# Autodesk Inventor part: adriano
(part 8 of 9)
sketch "スケッチ239"
  geometry: L1 (-4.75, 23.036)-(-9.75, 23.036) reference; L2 (-9.75, 23.036)-(-9.75, 20.036) reference; L3 (-9.75, 20.036)-(-4.75, 20.036) reference; L4 (-9.2, 22.536)-(-8.6, 22.536); L5 (-8.6, 22.536)-(-8.6, 20.836); L6 (-8.6, 20.836)-(-9.2, 20.836); L7 (-9.2, 20.836)-(-9.2, 22.536); L8 (-8.1, 22.536)-(-7.5, 22.536); L9 (-7.5, 22.536)-(-7.5, 20.836); L10 (-7.5, 20.836)-(-8.1, 20.836); L11 (-8.1, 20.836)-(-8.1, 22.536); L12 (-7, 22.536)-(-6.4, 22.536); L13 (-6.4, 22.536)-(-6.4, 20.836); L14 (-6.4, 20.836)-(-7, 20.836); L15 (-7, 20.836)-(-7, 22.536); L16 (-5.9, 22.536)-(-5.3, 22.536); L17 (-5.3, 22.536)-(-5.3, 20.836); L18 (-5.3, 20.836)-(-5.9, 20.836); L19 (-5.9, 20.836)-(-5.9, 22.536); L20 (31.3, 22.536)-(31.9, 22.536); L21 (31.9, 22.536)-(31.9, 20.836); L22 (31.9, 20.836)-(31.3, 20.836); L23 (31.3, 20.836)-(31.3, 22.536); L24 (32.4, 22.536)-(33, 22.536); L25 (33, 22.536)-(33, 20.836); L26 (33, 20.836)-(32.4, 20.836); L27 (32.4, 20.836)-(32.4, 22.536); L28 (33.5, 22.536)-(34.1, 22.536); L29 (34.1, 22.536)-(34.1, 20.836); L30 (34.1, 20.836)-(33.5, 20.836); L31 (33.5, 20.836)-(33.5, 22.536); L32 (34.6, 22.536)-(35.2, 22.536); L33 (35.2, 22.536)-(35.2, 20.836); L34 (35.2, 20.836)-(34.6, 20.836); L35 (34.6, 20.836)-(34.6, 22.536); L36 (30.75, 23.036)-(30.75, 20.036) reference; L37 (31.3, 5)-(31.9, 5); L38 (31.9, 5)-(31.9, 3.3); L39 (31.9, 3.3)-(31.3, 3.3); L40 (31.3, 3.3)-(31.3, 5); L41 (32.4, 5)-(33, 5); L42 (33, 5)-(33, 3.3); L43 (33, 3.3)-(32.4, 3.3); L44 (32.4, 3.3)-(32.4, 5); L45 (33.5, 5)-(34.1, 5); L46 (34.1, 5)-(34.1, 3.3); L47 (34.1, 3.3)-(33.5, 3.3); L48 (33.5, 3.3)-(33.5, 5); L49 (34.6, 5)-(35.2, 5); L50 (35.2, 5)-(35.2, 3.3); L51 (35.2, 3.3)-(34.6, 3.3); L52 (34.6, 3.3)-(34.6, 5); L53 (30.75, 2.5)-(35.75, 2.5) reference; L54 (35.75, 5.5)-(30.75, 5.5) reference; L55 (-6.4, 5)-(-7, 5); L56 (-7, 5)-(-7, 3.3); L57 (-7, 3.3)-(-6.4, 3.3); L58 (-6.4, 3.3)-(-6.4, 5); L59 (-7.5, 5)-(-8.1, 5); L60 (-8.1, 5)-(-8.1, 3.3); L61 (-8.1, 3.3)-(-7.5, 3.3); L62 (-7.5, 3.3)-(-7.5, 5); L63 (-8.6, 5)-(-9.2, 5); L64 (-9.2, 5)-(-9.2, 3.3)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; 1 further point
  constraints: 128 end point, 32 parallel, 16 horizontal, 16 perpendicular
  dimensions: "d4034" = 0.5 distance between parallel lines of L11 L5; "d4036" = 0.5 distance between parallel lines of L1 L8; "d4037" = 0 distance between parallel lines of L8 L12; "d4038" = 0 distance between parallel lines of L16 L12; "d4039" = 0 distance between parallel lines of L8 L4; "d4040" = 0.55 distance between parallel lines of L2 L7; "d4041" = 0.5 distance between parallel lines of L15 L9; "d4042" = 0.5 distance between parallel lines of L13 L19; "d4043" = 0.6 distance of L5.end L6.end; "d4044" = 0.6 distance of L9.end L10.end; "d4045" = 0.6 distance of L13.end L14.end; "d4046" = 0.6 distance of L17.end L18.end; "d4047" = 0.8 distance between parallel lines of L3 L6; "d4048" = 0.55 distance between parallel lines of L23 L36; "d4049" = 0.5 distance between parallel lines of L27 L21; "d4050" = 0.5 distance between parallel lines of L31 L25; "d4051" = 0.5 distance between parallel lines of L35 L29; "d4052" = 0.6 distance of L21.end L22.end; "d4053" = 0.6 distance of L25.end L26.end; "d4054" = 0.6 distance of L29.end L30.end; "d4055" = 0.6 distance of L33.end L34.end; "d4056" = 0.8 distance between parallel lines of L53 L39; "d4057" = 0 distance between parallel lines of L43 L39; "d4058" = 0 distance between parallel lines of L43 L47; "d4059" = 0 distance between parallel lines of L51 L47; "d4060" = 0.5 distance between parallel lines of L49 L54; "d4061" = 0 distance between parallel lines of L45 L49; "d4062" = 0 distance between parallel lines of L41 L45; "d4063" = 0 distance between parallel lines of L37 L41
extrude "押し出し228" cut sketch "スケッチ239" distance "d4065" = 0.5; taper "d4066" = 0 deg
fillet "フィレット5" dims "d4067" = 2
chamfer "面取り4" distance "d4068" = 0.4; stored, may be unused: second distance "d4069" = 2, angle "d4070" = 45 deg
sketch "スケッチ240"
  geometry: C1 r 1 at (5.162, -13.34); 1 further point
  constraints: 1 centre point
  dimensions: "d4071" = 2 diameter of C1
extrude "押し出し229" join sketch "スケッチ240" distance "d4073" = 16; taper "d4074" = 0 deg
sketch "スケッチ241"
  geometry: L1 (-0.4, 3)-(0.4, 3); L2 (0.4, 3)-(0.4, -3); L3 (0.4, -3)-(-0.4, -3); L4 (-0.4, -3)-(-0.4, 3); L5 (-3, 0.4)-(3, 0.4); L6 (3, 0.4)-(3, -0.4); L7 (3, -0.4)-(-3, -0.4); L8 (-3, -0.4)-(-3, 0.4); C1 r 1 at (0, 0) reference; 1 further point
  constraints: 16 end point, 4 parallel, 2 horizontal, 2 perpendicular
  dimensions: "d4075" = 6 distance of L1.end L2.end; "d4077" = 6 distance of L5.start L5.end; "d4078" = 0.4 distance from line of L4 C1.centre; "d4079" = 0.8 distance of L2.end L3.end; "d4080" = 0.4 distance from line of L5 C1.centre; "d4081" = 0.8 distance of L7.end L5.start; "d4082" = 3 distance from line of L1 C1.centre; "d4083" = 3 distance from line of L6 C1.centre
extrude "押し出し230" join sketch "スケッチ241" distance "d4084" = 32; taper "d4085" = 0 deg
sketch "スケッチ242"
  geometry: L1 (0.4, -3)-(0.4, -0.4) reference; L2 (0.4, -0.4)-(3, -0.4) reference; L3 (-0.4, 3)-(-0.4, 0.4) reference; L4 (-0.4, 0.4)-(-3, 0.4) reference; L5 (-0.4, 1.7)-(0.4, 1.7); L6 (0.4, 1.7)-(0.4, -1.7); L7 (0.4, -1.7)-(-0.4, -1.7); L8 (-0.4, -1.7)-(-0.4, 1.7); L9 (-1.7, 0.4)-(1.7, 0.4); L10 (1.7, 0.4)-(1.7, -0.4); L11 (1.7, -0.4)-(-1.7, -0.4); L12 (-1.7, -0.4)-(-1.7, 0.4); 1 further point
  constraints: 16 end point, 4 midpoint, 4 parallel, 2 horizontal, 2 perpendicular
extrude "押し出し231" join sketch "スケッチ242" distance "d4086" = 18; taper "d4087" = 0 deg
sketch "スケッチ243"
  geometry: C1 r 0.5 at (0, 0); 1 further point
  constraints: 1 centre point
  dimensions: "d4088" = 1 diameter of C1
extrude "押し出し232" join sketch "スケッチ243" distance "d4091" = 8; taper "d4092" = 0 deg
fillet "フィレット6" dims "d4093" = 1
chamfer "面取り5" distance "d4094" = 2; stored, may be unused: second distance "d4095" = 2, angle "d4096" = 45 deg
sketch "スケッチ244"
  geometry: L1 (112.588, 11.686)-(112.588, -18.314) reference; L2 (103.588, 31.686)-(112.588, 31.686) reference; C1 r 0.5 at (107.588, 23.686); C2 r 0.5 at (107.588, 15.686); C3 r 0.5 at (107.588, 7.686); 1 further point
  constraints: 3 centre point
  dimensions: "d4097" = 8 distance from line of C1.centre L2; "d4098" = 8 distance of C2.centre C1.centre; "d4099" = 8 distance of C3.centre C2.centre; "d4100" = 5 distance from line of C3.centre L1; "d4101" = 0 horizontal distance of C3.centre C2.centre; "d4102" = 0 horizontal distance of C1.centre C2.centre; "d4103" = 1 diameter of C1; "d4104" = 1 diameter of C2; "d4105" = 1 diameter of C3
extrude "table" join sketch "スケッチ244" distance "d4106" = 2; taper "d4107" = 0 deg
sketch "スケッチ245"
  geometry: C1 r 0.5 at (0, 0) reference; C2 r 1.5 at (0, 0); C3 r 1.5 at (0, -8); C4 r 1.5 at (0, -16); 1 further point
  constraints: 3 centre point, 1 coincident
  dimensions: "d4108" = 3 diameter of C2; "d4110" = 3 diameter of C3; "d4111" = 3 diameter of C4; "d4112" = 8 distance of C3.centre C1.centre; "d4113" = 8 distance of C4.centre C3.centre
extrude "押し出し234" join sketch "スケッチ245" distance "d4114" = 0.5; taper "d4115" = 0 deg
sketch "スケッチ246"
  geometry: L1 (113.588, 30.686)-(113.588, 11.686) reference; L2 (103.588, 31.686)-(112.588, 31.686) reference; L3 (106.688, 27.486)-(108.488, 27.486); L4 (108.488, 27.486)-(108.488, 25.686); L5 (108.488, 25.686)-(106.688, 25.686); L6 (106.688, 25.686)-(106.688, 27.486); L7 (109.488, 24.686)-(111.288, 24.686); L8 (111.288, 24.686)-(111.288, 22.886); L9 (111.288, 22.886)-(109.488, 22.886); L10 (109.488, 22.886)-(109.488, 24.686); L11 (105.688, 24.686)-(103.888, 24.686); L12 (103.888, 24.686)-(103.888, 22.886); L13 (103.888, 22.886)-(105.688, 22.886); L14 (105.688, 22.886)-(105.688, 24.686); L15 (106.688, 21.686)-(108.488, 21.686); L16 (108.488, 21.686)-(108.488, 19.886); L17 (108.488, 19.886)-(106.688, 19.886); L18 (106.688, 19.886)-(106.688, 21.686); L19 (106.688, 19.386)-(108.488, 19.386); L20 (108.488, 19.386)-(108.488, 17.586); L21 (108.488, 17.586)-(106.688, 17.586); L22 (106.688, 17.586)-(106.688, 19.386); L23 (109.688, 16.586)-(111.488, 16.586); L24 (111.488, 16.586)-(111.488, 14.786); L25 (111.488, 14.786)-(109.688, 14.786); L26 (109.688, 14.786)-(109.688, 16.586); L27 (105.688, 16.586)-(103.888, 16.586); L28 (103.888, 16.586)-(103.888, 14.786); L29 (103.888, 14.786)-(105.688, 14.786); L30 (105.688, 14.786)-(105.688, 16.586); L31 (106.688, 13.786)-(108.488, 13.786); L32 (108.488, 13.786)-(108.488, 11.986); L33 (108.488, 11.986)-(106.688, 11.986); L34 (106.688, 11.986)-(106.688, 13.786); L35 (106.688, 11.486)-(108.488, 11.486); L36 (108.488, 11.486)-(108.488, 9.686); L37 (108.488, 9.686)-(106.688, 9.686); L38 (106.688, 9.686)-(106.688, 11.486); L39 (109.488, 8.686)-(111.288, 8.686); L40 (111.288, 8.686)-(111.288, 6.886); L41 (111.288, 6.886)-(109.488, 6.886); L42 (109.488, 6.886)-(109.488, 8.686); L43 (106.688, 5.886)-(108.488, 5.886); L44 (108.488, 5.886)-(108.488, 4.086); L45 (108.488, 4.086)-(106.688, 4.086); L46 (106.688, 4.086)-(106.688, 5.886); L47 (104.427, 8.486)-(104.688, 6.705); L48 (104.688, 6.705)-(102.907, 6.444); L49 (102.907, 6.444)-(102.646, 8.225); L50 (102.646, 8.225)-(104.427, 8.486); 1 further point
  constraints: 96 end point, 24 parallel, 12 perpendicular, 11 horizontal
  dimensions: "d4124" = 1.8 distance of L3.end L4.end; "d4126" = 1.8 distance of L7.end L8.end; "d4127" = 1.8 distance of L3.start L3.end; "d4128" = 2.3 distance between parallel lines of L8 L1; "d4129" = 1 distance between parallel lines of L10 L4; "d4130" = 1.8 distance of L7.start L7.end; "d4131" = 4.2 distance between parallel lines of L3 L2; "d4132" = 1 distance between parallel lines of L7 L5; "d4133" = 1.8 distance of L11.start L11.end; "d4134" = 1 distance between parallel lines of L6 L14; "d4135" = 1.8 distance of L15.end L16.end; "d4136" = 1.2 distance between parallel lines of L15 L9; "d4137" = 1.8 distance of L21.end L19.start; "d4138" = 0 distance between parallel lines of L7 L11; "d4139" = 0 distance between parallel lines of L9 L13; "d4140" = 0 distance between parallel lines of L16 L4; "d4141" = 0 distance between parallel lines of L18 L6; "d4142" = 0 distance between parallel lines of L22 L18; "d4143" = 0 distance between parallel lines of L20 L16; "d4144" = 0.5 distance between parallel lines of L19 L17; "d4145" = 1 distance between parallel lines of L23 L21; "d4146" = 1.8 distance of L23.end L24.end; "d4147" = 1 distance between parallel lines of L31 L25; "d4148" = 1.8 distance of L31.end L32.end; "d4149" = 0.5 distance between parallel lines of L35 L33; "d4150" = 1.8 distance of L35.end L36.end; "d4151" = 1 distance between parallel lines of L39 L37; "d4152" = 1.8 distance of L39.end L40.end; "d4153" = 1.8 distance of L43.end L44.end; "d4154" = 1 distance between parallel lines of L43 L41; "d4155" = 2 distance from line of L46 L47.end; "d4156" = 0 distance between parallel lines of L46 L38; "d4157" = 0 distance between parallel lines of L38 L34; "d4158" = 1.8 distance of L31.start L31.end; "d4159" = 0 distance between parallel lines of L32 L20; "d4161" = 1.8 distance between parallel lines of L47 L49; "d4162" = 1.8 distance between parallel lines of L48 L50; "d4163" = 1.2 distance from line of L47.start L37; "d4365" = 0 distance between parallel lines of L28 L12; "d4366" = 2.1 distance between parallel lines of L1 L24; "d4367" = 1.8 distance between parallel lines of L24 L26
extrude "押し出し235" join sketch "スケッチ246" distance "d4164" = 3; taper "d4165" = 0 deg
sketch "スケッチ247"
  geometry: L1 (106.688, 27.486)-(106.688, 25.686) reference; L2 (108.488, 25.686)-(108.488, 27.486) reference; L3 (109.488, 24.687)-(110.688, 24.687); L4 (110.688, 24.687)-(110.688, 22.886); L5 (110.688, 22.886)-(109.488, 22.886); L6 (109.488, 22.886)-(109.488, 24.687); L7 (105.688, 24.687)-(104.488, 24.687); L8 (104.488, 24.687)-(104.488, 22.886); L9 (104.488, 22.886)-(105.688, 22.886); L10 (105.688, 22.886)-(105.688, 24.687); L11 (106.688, 21.686)-(108.488, 21.686); L12 (108.488, 21.686)-(108.488, 20.486); L13 (108.488, 20.486)-(106.688, 20.486); L14 (106.688, 20.486)-(106.688, 21.686); L15 (106.688, 17.586)-(108.488, 17.586); L16 (108.488, 17.586)-(108.488, 18.786); L17 (108.488, 18.786)-(106.688, 18.786); L18 (106.688, 18.786)-(106.688, 17.586); L19 (105.688, 16.586)-(104.488, 16.586); L20 (104.488, 16.586)-(104.488, 14.786); L21 (104.488, 14.786)-(105.688, 14.786); L22 (105.688, 14.786)-(105.688, 16.586); L23 (109.688, 16.586)-(110.888, 16.586); L24 (110.888, 16.586)-(110.888, 14.786); L25 (110.888, 14.786)-(109.688, 14.786); L26 (109.688, 14.786)-(109.688, 16.586); L27 (106.688, 13.786)-(108.488, 13.786); L28 (108.488, 13.786)-(108.488, 12.586); L29 (108.488, 12.586)-(106.688, 12.586); L30 (106.688, 12.586)-(106.688, 13.786); L31 (106.688, 9.686)-(108.488, 9.686); L32 (108.488, 9.686)-(108.488, 10.886); L33 (108.488, 10.886)-(106.688, 10.886); L34 (106.688, 10.886)-(106.688, 9.686); L35 (109.488, 8.686)-(110.688, 8.686); L36 (110.688, 8.686)-(110.688, 6.872); L37 (110.688, 6.872)-(109.488, 6.872); L38 (109.488, 6.872)-(109.488, 8.686); L39 (106.688, 5.886)-(108.488, 5.886); L40 (108.488, 5.886)-(108.488, 4.686); L41 (108.488, 4.686)-(106.688, 4.686); L42 (106.688, 4.686)-(106.688, 5.886); L43 (106.688, 26.886)-(108.488, 26.886); L44 (108.488, 26.886)-(108.488, 25.686); L45 (108.488, 25.686)-(106.688, 25.686); L46 (106.688, 25.686)-(106.688, 26.886); L47 (103.888, 24.686)-(103.888, 22.886) reference; L48 (103.888, 22.886)-(105.688, 22.886) reference; L49 (109.488, 22.886)-(111.288, 22.886) reference; L50 (108.488, 21.686)-(106.688, 21.686) reference; L51 (106.688, 17.586)-(108.488, 17.586) reference; L52 (109.688, 16.586)-(109.688, 14.786) reference; L53 (111.488, 16.586)-(109.688, 16.586) reference; L54 (105.688, 14.786)-(105.688, 16.586) reference; L55 (103.888, 14.786)-(105.688, 14.786) reference; L56 (106.688, 9.686)-(108.488, 9.686) reference; L57 (108.488, 13.786)-(106.688, 13.786) reference; L58 (109.488, 8.686)-(109.488, 6.886) reference; L59 (111.288, 8.686)-(109.488, 8.686) reference; L60 (108.488, 5.886)-(106.688, 5.886) reference; L61 (104.515, 8.586)-(104.788, 6.706); L62 (104.788, 6.706)-(103.502, 6.519); L63 (103.502, 6.519)-(103.228, 8.399); L64 (103.228, 8.399)-(104.515, 8.586)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; 1 further point
  constraints: 96 end point, 24 parallel, 12 perpendicular, 11 horizontal, 6 point on line
  dimensions: "d4166" = 1.2 distance of L43.end L2.start; "d4167" = 1.2 distance of L3.start L3.end; "d4168" = 1.2 distance of L7.start L7.end; "d4169" = 0.6 distance between parallel lines of L47 L8; "d4170" = 0 distance between parallel lines of L9 L48; "d4171" = 0 distance between parallel lines of L5 L49; "d4172" = 1.2 distance of L11.end L12.end; "d4173" = 0 distance between parallel lines of L50 L11; "d4174" = 1.2 distance of L15.end L16.end; "d4175" = 0 distance between parallel lines of L51 L15; "d4176" = 1.2 distance of L23.start L23.end; "d4177" = 0 distance between parallel lines of L52 L26; "d4178" = 0 distance between parallel lines of L23 L53; "d4179" = 0 distance between parallel lines of L22 L54; "d4180" = 1.2 distance of L19.start L19.end; "d4181" = 0 distance between parallel lines of L55 L21; "d4182" = 1.8 distance of L19.end L20.end; "d4183" = 1.8 distance of L23.end L24.end; "d4184" = 1.2 distance of L27.end L28.end; "d4185" = 1.2 distance of L31.end L32.end; "d4186" = 0 distance between parallel lines of L31 L56; "d4187" = 0 distance between parallel lines of L27 L57; "d4188" = 1.2 distance of L35.start L35.end; "d4189" = 0 distance between parallel lines of L38 L58; "d4190" = 0 distance between parallel lines of L59 L35; "d4191" = 0 distance between parallel lines of L60 L39; "d4192" = 1.2 distance of L39.end L40.end; "d4193" = 1.3 distance between parallel lines of L61 L63; "d4194" = 1.9 distance between parallel lines of L62 L64; "d4197" = 1.8 distance of L32.end L33.end; "d4198" = 1.9 distance from line of L42 L61.end; "d4199" = 0 distance between parallel lines of L42 L34; "d4200" = 1.1 distance from line of L31 L61.start; "d4203" = 0 distance between parallel lines of L6 L66; "d4368" = 0 distance between parallel lines of L18 L14
extrude "押し出し236" cut sketch "スケッチ247" distance "d4201" = 1.5; taper "d4202" = 0 deg
sketch "スケッチ249"
  geometry: L1 (1.8, 0)-(0, 0) reference; L2 (0.6, 0)-(1.2, 0); L3 (1.2, 0)-(1.2, 0.6); L4 (1.2, 0.6)-(0.6, 0.6); L5 (0.6, 0.6)-(0.6, 0); 1 further point
  constraints: 8 end point, 2 parallel, 1 horizontal, 1 perpendicular, 1 point on line
  dimensions: "d4204" = 0.6 distance of L2.end L3.end; "d4206" = 0.6 distance of L3.end L4.end
extrude "押し出し237" cut sketch "スケッチ249" distance "d4207" = 20; taper "d4208" = 0 deg
sketch "スケッチ250"
  geometry: L1 (1.8, 0)-(0, 0) reference; L2 (1.2, 0)-(0.6, 0); L3 (0.6, 0)-(0.6, 0.6); L4 (0.6, 0.6)-(1.2, 0.6); L5 (1.2, 0.6)-(1.2, 0); 1 further point
  constraints: 8 end point, 2 parallel, 1 horizontal, 1 perpendicular, 1 point on line
  dimensions: "d4209" = 0.6 distance of L4.end L2.start; "d4211" = 0.6 distance of L3.end L4.end
extrude "押し出し238" cut sketch "スケッチ250" distance "d4212" = 12; taper "d4213" = 0 deg
sketch "スケッチ251"
  geometry: L1 (-0.952, -0.5)-(-1.8, -0.5) reference; L2 (-1.376, -0.5)-(-0.826, -0.5); L3 (-0.826, -0.5)-(-0.826, 0.1); L4 (-0.826, 0.1)-(-1.376, 0.1); L5 (-1.376, 0.1)-(-1.376, -0.5); 2 further points
  constraints: 8 end point, 2 parallel, 1 horizontal, 1 midpoint, 1 perpendicular
  dimensions: "d4214" = 0.6 distance of L4.end L2.start; "d4216" = 0.55 distance of L3.end L4.end
extrude "押し出し239" cut sketch "スケッチ251" distance "d4217" = 4; taper "d4218" = 0 deg
sketch "スケッチ253"
  geometry: L1 (1.8, 0)-(0, 0) reference; L2 (0.6, 0)-(1.2, 0); L3 (1.2, 0)-(1.2, 0.6); L4 (1.2, 0.6)-(0.6, 0.6); L5 (0.6, 0.6)-(0.6, 0); L6 (6.4, 0.6)-(7, 0.6); L7 (7, 0.6)-(7, 0); L8 (7, 0)-(6.4, 0); L9 (6.4, 0)-(6.4, 0.6); L10 (8.8, 0.6)-(9.4, 0.6); L11 (9.4, 0.6)-(9.4, 0); L12 (9.4, 0)-(8.8, 0); L13 (8.8, 0)-(8.8, 0.6); L14 (14.4, 0.6)-(15, 0.6); L15 (15, 0.6)-(15, 0); L16 (15, 0)-(14.4, 0); L17 (14.4, 0)-(14.4, 0.6); L18 (16.6, 0.6)-(17.2, 0.6); L19 (17.2, 0.6)-(17.2, 0); L20 (17.2, 0)-(16.6, 0); L21 (16.6, 0)-(16.6, 0.6); L22 (22.2, 0.6)-(22.8, 0.6); L23 (22.8, 0.6)-(22.8, 0); L24 (22.8, 0)-(22.2, 0); L25 (22.2, 0)-(22.2, 0.6); 1 further point
  constraints: 48 end point, 12 parallel, 6 horizontal, 6 perpendicular, 5 point on line
  dimensions: "d4219" = 0.6 distance of L3.end L4.end; "d4221" = 0.6 distance of L6.start L6.end; "d4222" = 0.6 distance of L10.start L10.end; "d4223" = 0.6 distance of L14.start L14.end; "d4224" = 0.6 distance of L18.start L18.end; "d4225" = 5.2 distance between parallel lines of L9 L3; "d4226" = 1.8 distance between parallel lines of L13 L7; "d4227" = 5 distance between parallel lines of L17 L11; "d4228" = 1.6 distance between parallel lines of L21 L15; "d4229" = 0.6 distance of L22.start L22.end; "d4230" = 5 distance between parallel lines of L25 L19; "d4231" = 0.6 distance of L2.end L3.end; "d4232" = 0 distance between parallel lines of L6 L4; "d4233" = 0 distance between parallel lines of L24 L20
extrude "押し出し240" cut sketch "スケッチ253" distance "d4234" = 3; taper "d4235" = 0 deg
fillet "フィレット7" dims "d4236" = 0.5
fillet "フィレット11" dims "d4240" = 2
sketch "スケッチ254"
  geometry: L1 (-0.115, 24.135)-(0.885, 24.135); L2 (0.885, 24.135)-(0.885, -0.31); L3 (0.885, -0.31)-(-0.115, -0.31); L4 (-0.115, -0.31)-(-0.115, 24.135); L5 (0.785, -0.634)-(0.785, 24.113) reference; 1 further point
  constraints: 8 end point, 2 parallel, 1 horizontal, 1 perpendicular
  dimensions: "d4243" = 1 distance of L2.end L3.end; "d4245" = 0.1 distance between parallel lines of L5 L2
extrude "押し出し241" join sketch "スケッチ254" distance "d4241" = 0.5; taper "d4242" = 0 deg
sketch "スケッチ255"
  geometry: L1 (0.001, 0.961)-(24.532, 0.961); L2 (24.532, 0.961)-(24.532, -0.039); L3 (24.532, -0.039)-(0.001, -0.039); L4 (0.001, -0.039)-(0.001, 0.961); 1 further point
  constraints: 8 end point, 2 parallel, 1 horizontal, 1 perpendicular
  dimensions: "d4246" = 1 distance of L1.end L2.end
extrude "押し出し242" join sketch "スケッチ255" distance "d4248" = 0.5; taper "d4249" = 0 deg; dims "d1246" = 0
sketch "スケッチ256"
  geometry: L1 (24.669, -0.79)-(24.671, -0.696) reference; L2 (24.671, -0.696)-(24.029, 0) reference; L3 (24.029, 0)-(0, 0) reference; L4 (0, 0)-(-0.428, -0.262) reference; L5 (-0.439, -0.79)-(-0.428, -0.262) reference; L6 (-0.439, -0.79)-(24.669, -0.79) reference; L7 (-0.455, 0.138)-(24.487, 0.138); L8 (24.487, 0.138)-(24.487, -0.862); L9 (24.487, -0.862)-(-0.455, -0.862); L10 (-0.455, -0.862)-(-0.455, 0.138); 1 further point
  constraints: 8 end point, 2 parallel, 1 horizontal, 1 perpendicular
  dimensions: "d4250" = 1 distance of L7.end L8.end
extrude "押し出し243" join sketch "スケッチ256" distance "d4252" = 0.5; taper "d4253" = 0 deg
sketch "スケッチ258"
  geometry: L1 (-24.462, -0.711)-(-24.462, -0.787) reference; L2 (-24.531, -0.79)-(0, 0) reference; L3 (0, 0)-(0, 0.525) reference; L4 (0, 0.525)-(-0.412, 0.769) reference; L5 (-0.412, 0.769)-(-23.824, 0.015) reference; L6 (-23.824, 0.015)-(-24.531, -0.79) reference; L7 (-0.015, 0.9)-(-24.313, 0.118); L8 (-24.313, 0.118)-(-24.281, -0.882); L9 (-24.281, -0.882)-(0.017, -0.1); L10 (0.017, -0.1)-(-0.015, 0.9); 1 further point
  constraints: 8 end point, 2 parallel, 2 perpendicular
  dimensions: "d4254" = 1 distance between parallel lines of L9 L7; "d4257" = 0.1 distance between parallel lines of L9 L2
extrude "押し出し244" join sketch "スケッチ258" distance "d4258" = 0.5; taper "d4259" = 0 deg
sketch "スケッチ259"
  geometry: L1 (0, 23.758)-(0, 0) reference; L2 (0.781, 0.02)-(0.781, 24.416) reference; L3 (-0.119, 24.077)-(-0.119, -0.044); L4 (-0.119, -0.044)-(0.881, -0.044); L5 (0.881, -0.044)-(0.881, 24.077); L6 (0.881, 24.077)-(-0.119, 24.077); 1 further point
  constraints: 8 end point, 2 parallel, 2 perpendicular
  dimensions: "d4260" = 1 distance of L5.end L3.start; "d4262" = 0.1 distance between parallel lines of L2 L5
extrude "押し出し245" join sketch "スケッチ259" distance "d4263" = 0.5; taper "d4264" = 0 deg; dims "d1290" = 0, "d1292" = 0
sketch "スケッチ260"
  geometry: L1 (0.737, 25.022)-(0.643, 25.022) reference; L2 (0.643, 25.022)-(0, 0) reference; L3 (0, 0)-(0.789, 0) reference; L4 (0.789, 0)-(1.416, 24.368) reference; L5 (1.416, 24.368)-(0.737, 25.022) reference; L6 (0.524, 24.718)-(-0.113, -0.039); L7 (-0.113, -0.039)-(0.887, -0.065); L8 (0.887, -0.065)-(1.524, 24.693); L9 (1.524, 24.693)-(0.524, 24.718); 1 further point
  constraints: 8 end point, 2 parallel, 2 perpendicular
  dimensions: "d4265" = 1 horizontal distance of L8.end L6.start; "d4267" = 0.1 distance between parallel lines of L4 L8
extrude "押し出し246" join sketch "スケッチ260" distance "d4268" = 0.5; taper "d4269" = 0 deg; dims "d1285" = 0
sketch "スケッチ261"
  geometry: L1 (-0.25, 1.6)-(0.25, 1.6); L2 (0.25, 1.6)-(0.25, -0.2); L3 (0.25, -0.2)-(-0.25, -0.2); L4 (-0.25, -0.2)-(-0.25, 1.6); L5 (-0.3, -0.15)-(-0.072, 0.295); L6 (-0.072, 0.295)-(1.174, -0.344); L7 (1.174, -0.344)-(0.946, -0.789); L8 (0.946, -0.789)-(-0.3, -0.15); C1 r 2.024 at (0, 0) reference; 1 further point
  constraints: 16 end point, 4 parallel, 2 perpendicular, 1 horizontal
  dimensions: "d4270" = 0.5 distance of L1.start L1.end; "d4272" = 0.25 distance from line of L2 C1.centre; "d4273" = 0.2 distance from line of L3 C1.centre; "d4274" = 1.8 distance of L3.end L1.start; "d4275" = 0.5 distance between parallel lines of L8 L6; "d4276" = 1.4 distance between parallel lines of L7 L5; "d4277" = 0.3 horizontal distance of C1.centre L5.start; "d4278" = 1.75 distance from line of L5.start L1
extrude "押し出し247" join sketch "スケッチ261" distance "d4279" = 0.5; taper "d4280" = 0 deg
sketch "スケッチ262"
  geometry: C1 r 0.2 at (0, 0); 1 further point
  constraints: 1 centre point
  dimensions: "d4281" = 0.4 diameter of C1
extrude "押し出し248" join sketch "スケッチ262" distance "d4285" = 0.5; taper "d4286" = 0 deg
sketch "スケッチ263"
  geometry: C1 r 0.3 at (0, 0) reference; C2 r 0.5 at (0, 0) reference; C3 r 0.8 at (0, 0); 1 further point
  constraints: 1 centre point, 1 coincident
  dimensions: "d4287" = 1.6 diameter of C3
extrude "押し出し249" join sketch "スケッチ263" distance "d4289" = 0.4; taper "d4290" = 0 deg
fillet "フィレット12" dims "d4291" = 0.2
fillet "フィレット13" dims "d4292" = 0.2
sketch "スケッチ264"
  geometry: L1 (-20.412, 19.314)-(-14.412, 19.314); L2 (-14.412, 19.314)-(-14.412, 13.314); L3 (-14.412, 13.314)-(-20.412, 13.314); L4 (-20.412, 13.314)-(-20.412, 19.314); 1 further point
  constraints: 8 end point, 2 parallel, 1 horizontal, 1 perpendicular
  dimensions: "d4293" = 6 distance of L1.start L1.end; "d4294" = 6 distance of L3.end L1.start
extrude "押し出し250" join sketch "スケッチ264" distance "d4295" = 38; taper "d4296" = 0 deg
fillet "フィレット15" dims "d4313" = 1
sketch "スケッチ268"
  geometry: L1 (119.588, -39.314)-(119.588, 40.686) reference; L2 (117.388, -36.358)-(118.588, -36.358); L3 (118.588, -36.358)-(118.588, -37.558); L4 (118.588, -37.558)-(117.388, -37.558); L5 (117.388, -37.558)-(117.388, -36.358); L6 (117.388, -31.158)-(118.588, -31.158); L7 (118.588, -31.158)-(118.588, -32.358); L8 (118.588, -32.358)-(117.388, -32.358); L9 (117.388, -32.358)-(117.388, -31.158); L10 (117.388, -25.958)-(118.588, -25.958); L11 (118.588, -25.958)-(118.588, -27.158); L12 (118.588, -27.158)-(117.388, -27.158); L13 (117.388, -27.158)-(117.388, -25.958); L14 (117.388, -20.758)-(118.588, -20.758); L15 (118.588, -20.758)-(118.588, -21.958); L16 (118.588, -21.958)-(117.388, -21.958); L17 (117.388, -21.958)-(117.388, -20.758); 1 further point
  constraints: 32 end point, 8 parallel, 4 horizontal, 4 perpendicular
  dimensions: "d4327" = 1.2 distance of L2.end L3.end; "d4328" = 4 distance between parallel lines of L8 L2; "d4329" = 4 distance between parallel lines of L12 L6; "d4330" = 4 distance between parallel lines of L10 L16; "d4331" = 1.2 distance of L6.end L7.end; "d4332" = 1.2 distance of L10.end L11.end; "d4333" = 1.2 distance of L14.end L15.end; "d4334" = 1.2 distance of L3.end L4.end; "d4335" = 1 distance between parallel lines of L1 L3; "d4336" = 0 distance between parallel lines of L9 L5; "d4337" = 0 distance between parallel lines of L13 L9; "d4338" = 0 distance between parallel lines of L17 L13
extrude "押し出し253" join sketch "スケッチ268" distance "d4339" = 1; taper "d4340" = 0 deg
sketch "スケッチ269"
  geometry: L1 (118.588, -36.358)-(117.388, -36.358) reference; L2 (118.588, -37.558)-(118.588, -36.358) reference; L3 (118.588, -37.558)-(116.588, -37.558); L4 (116.588, -37.558)-(116.588, -36.358); L5 (116.588, -36.358)-(118.588, -36.358); L6 (118.588, -36.358)-(118.588, -37.558); L7 (118.588, -32.358)-(116.588, -32.358); L8 (116.588, -32.358)-(116.588, -31.158); L9 (116.588, -31.158)-(118.588, -31.158); L10 (118.588, -31.158)-(118.588, -32.358); L11 (118.588, -27.158)-(116.588, -27.158); L12 (116.588, -27.158)-(116.588, -25.958); L13 (116.588, -25.958)-(118.588, -25.958); L14 (118.588, -25.958)-(118.588, -27.158); L15 (118.588, -21.958)-(116.588, -21.958); L16 (116.588, -21.958)-(116.588, -20.758); L17 (116.588, -20.758)-(118.588, -20.758); L18 (118.588, -20.758)-(118.588, -21.958); 1 further point
  constraints: 32 end point, 8 parallel, 4 horizontal, 4 perpendicular
  dimensions: "d4341" = 2 distance of L2.start L3.end; "d4342" = 0 distance between parallel lines of L4 L8; "d4343" = 0 distance between parallel lines of L12 L8; "d4344" = 0 distance between parallel lines of L12 L16; "d4345" = 0 distance between parallel lines of L10 L2; "d4346" = 0 distance between parallel lines of L10 L14; "d4347" = 0 distance between parallel lines of L14 L18; "d4348" = 4 distance between parallel lines of L1 L7; "d4349" = 1.2 distance of L9.end L7.start; "d4350" = 4 distance between parallel lines of L11 L9; "d4351" = 1.2 distance of L13.end L11.start; "d4352" = 4 distance between parallel lines of L15 L13; "d4353" = 1.2 distance of L17.end L15.start
extrude "押し出し254" join sketch "スケッチ269" distance "d4354" = 1; taper "d4355" = 0 deg
fillet "フィレット16" dims "d4356" = 0.5
sketch "スケッチ270"
  geometry: L1 (0.8, 2.6)-(1.8, 2.6) reference; L2 (0.8, 2.6)-(1.8, 2.6); A1 r 0.5 centre (1.3, 2.6) between (1.8, 2.6) and (0.8, 2.6); 1 further point
  constraints: 2 end point, 2 point on circle, 1 centre point, 1 collinear, 1 midpoint
extrude "押し出し255" cut sketch "スケッチ270" distance "d4357" = 5; taper "d4358" = 0 deg
sketch "スケッチ271"
  geometry: L1 (0.8, 2.6)-(1.8, 2.6) reference; L2 (0.8, 2.6)-(1.8, 2.6); A1 r 0.5 centre (1.3, 2.6) between (1.8, 2.6) and (0.8, 2.6); 1 further point
  constraints: 2 end point, 2 point on circle, 1 centre point, 1 collinear, 1 midpoint
extrude "押し出し256" cut sketch "スケッチ271" distance "d4359" = 5; taper "d4360" = 0 deg
sketch "スケッチ272"
  geometry: L1 (60.088, -11.414)-(29.643, -11.414) reference; L2 (29.088, -10.858)-(29.643, -11.414) reference; L3 (29.088, -10.858)-(29.088, 10.23) reference; L4 (29.088, 10.23)-(29.007, 10.149) reference; L5 (29.007, 10.149)-(28.978, 10.179) reference; L6 (28.978, 10.179)-(29.688, 10.883) reference; L7 (29.688, 10.883)-(29.714, 10.857) reference; L8 (29.714, 10.857)-(29.643, 10.786) reference; L9 (29.643, 10.786)-(60.088, 10.786) reference; L10 (58.588, -11.414)-(29.088, -11.414); L11 (29.088, -11.414)-(29.088, -9.414); L12 (29.088, -9.414)-(58.588, -9.414); L13 (58.588, -9.414)-(58.588, -11.414); L14 (58.588, 10.786)-(29.088, 10.786); L15 (29.088, 10.786)-(29.088, 8.786); L16 (29.088, 8.786)-(58.588, 8.786); L17 (58.588, 8.786)-(58.588, 10.786); 1 further point
  constraints: 16 end point, 4 parallel, 4 point on line, 2 horizontal, 2 perpendicular
  dimensions: "d4369" = 2 distance of L14.end L15.end; "d4371" = 2 distance of L10.end L11.end
extrude "押し出し257" join sketch "スケッチ272" distance "d4372" = 2; taper "d4373" = 0 deg
fillet "フィレット17" dims "d4374" = 1
sketch "スケッチ283"
  geometry: L1 (-20.412, 19.314)-(11.588, 19.314) reference; L2 (-19.412, 19.314)-(-73.412, 19.314); L3 (-73.412, 19.314)-(-73.412, 16.314); L4 (-73.412, 16.314)-(-79.412, 16.314); L5 (-79.412, 16.314)-(-79.412, -10.686); L6 (-79.412, -10.686)-(-54.412, -10.686); L7 (-54.412, -10.686)-(-39.412, -20.686); L8 (-39.412, -20.686)-(-19.412, -20.686); L9 (-19.412, -20.686)-(-19.412, 19.314); L10 (-20.412, -15.686)-(-20.412, 19.314) reference; L11 (-20.412, -10.686)-(2.388, -10.686) reference; 1 further point
  constraints: 16 end point, 5 perpendicular, 1 horizontal, 1 parallel, 1 point on line
  dimensions: "d4426" = 1 distance between parallel lines of L10 L9; "d4427" = 3 distance of L2.end L3.end; "d4428" = 6 distance of L3.end L4.end; "d4429" = 0 distance between parallel lines of L6 L11; "d4430" = 40 distance of L8.end L2.start; "d4431" = 20 distance of L7.end L8.end; "d4432" = 25 distance of L5.end L6.end; "d4433" = 60 distance between parallel lines of L5 L9
extrude "押し出し266" join sketch "スケッチ283" distance "d4434" = 40; taper "d4435" = 0 deg
sketch "スケッチ284"
  geometry: L1 (-20.412, 19.686)-(-39.412, 19.686); L2 (-19.412, 20.686)-(-39.412, 20.686) reference; L3 (-39.412, 19.686)-(-54.412, 9.686); L4 (-54.412, 9.686)-(-72.412, 9.686); L5 (-72.412, 9.686)-(-72.412, -18.314); L6 (-72.412, -18.314)-(-20.412, -18.314); L7 (-20.412, -19.314)-(-20.412, 10.686) reference; L8 (-20.412, 19.686)-(-20.412, -18.314); L9 (-19.412, 10.686)-(-19.412, 20.686) reference; L10 (-73.412, -19.314)-(-20.412, -19.314) reference; L11 (-73.412, -16.314)-(-73.412, -19.314) reference; L12 (-54.412, 10.686)-(-79.412, 10.686) reference; 1 further point
  constraints: 12 end point, 2 parallel, 2 perpendicular, 1 point on line
  dimensions: "d4436" = 1 distance from line of L9 L1.start; "d4437" = 1 distance between parallel lines of L2 L1; "d4438" = 1 distance between parallel lines of L6 L10; "d4439" = 1 distance between parallel lines of L11 L5; "d4440" = 1 distance between parallel lines of L12 L4; "d4441" = 0 horizontal distance of L12.start L3.end
extrude "押し出し267" cut sketch "スケッチ284" distance "d4442" = 4; taper "d4443" = 0 deg
sketch "スケッチ285"
  geometry: L1 (-20.412, 19.686)-(-20.412, 10.686) reference; L2 (-20.412, -18.314)-(-72.412, -18.314) reference; L3 (-20.412, 19.686)-(-35.412, 19.686); L4 (-35.412, 19.686)-(-35.412, -18.314); L5 (-35.412, -18.314)-(-20.412, -18.314); L6 (-20.412, -18.314)-(-20.412, 19.686); 1 further point
  constraints: 8 end point, 2 parallel, 1 horizontal, 1 perpendicular, 1 point on line
  dimensions: "d4444" = 15 distance between parallel lines of L4 L6
extrude "押し出し268" cut sketch "スケッチ285" distance "d4445" = 0.5; taper "d4446" = 0 deg
sketch "スケッチ286"
  geometry: L1 (-20.412, 19.686)-(-20.412, 10.686) reference; L2 (-20.412, -18.314)-(-35.412, -18.314) reference; L3 (-20.412, 19.686)-(-30.412, 19.686); L4 (-30.412, 19.686)-(-30.412, -18.314); L5 (-30.412, -18.314)-(-20.412, -18.314); L6 (-20.412, -18.314)-(-20.412, 19.686); 1 further point
  constraints: 8 end point, 2 parallel, 1 horizontal, 1 perpendicular, 1 point on line
  dimensions: "d4447" = 10 distance between parallel lines of L4 L6
extrude "押し出し269" cut sketch "スケッチ286" distance "d4448" = 0.5; taper "d4449" = 0 deg
sketch "スケッチ287"
  geometry: L1 (-20.412, 19.686)-(-20.412, 10.686) reference; L2 (-20.412, -18.314)-(-30.412, -18.314) reference; L3 (-20.412, 19.686)-(-25.412, 19.686); L4 (-25.412, 19.686)-(-25.412, -18.314); L5 (-25.412, -18.314)-(-20.412, -18.314); L6 (-20.412, -18.314)-(-20.412, 19.686); 1 further point
  constraints: 8 end point, 2 parallel, 1 horizontal, 1 midpoint, 1 perpendicular
  dimensions: "d4450" = 5 distance between parallel lines of L4 L6
extrude "押し出し270" cut sketch "スケッチ287" distance "d4451" = 0.5; taper "d4452" = 0 deg
sketch "スケッチ288"
  geometry: L1 (-79.412, 10.686)-(-79.412, -16.314) reference; L2 (-54.412, 10.686)-(-79.412, 10.686) reference; L3 (-79.412, -16.314)-(-73.412, -16.314); L4 (-73.412, -16.314)-(-73.412, 10.686); L5 (-73.412, 10.686)-(-79.412, 10.686); L6 (-79.412, 10.686)-(-79.412, -16.314); L7 (-72.412, -18.314)-(-72.412, 9.686) reference; 1 further point
  constraints: 8 end point, 2 parallel, 1 horizontal, 1 perpendicular, 1 point on line
  dimensions: "d4453" = 1 distance between parallel lines of L4 L7
extrude "押し出し271" cut sketch "スケッチ288" distance "d4454" = 2; taper "d4455" = 0 deg
sketch "スケッチ289"
  geometry: L1 (-73.412, 10.686)-(-73.412, -19.314) reference; L2 (-78.412, -15.314)-(-73.412, -15.314); L3 (-73.412, -15.314)-(-73.412, 9.686); L4 (-73.412, 9.686)-(-78.412, 9.686); L5 (-78.412, 9.686)-(-78.412, -15.314); L6 (-79.412, 10.686)-(-73.412, 10.686) reference; L7 (-73.412, -16.314)-(-79.412, -16.314) reference; L8 (-79.412, -16.314)-(-79.412, 10.686) reference; 1 further point
  constraints: 8 end point, 2 parallel, 1 horizontal, 1 perpendicular, 1 point on line
  dimensions: "d4456" = 1 distance between parallel lines of L6 L4; "d4457" = 1 distance between parallel lines of L2 L7; "d4458" = 1 distance between parallel lines of L8 L5
extrude "押し出し272" cut sketch "スケッチ289" distance "d4459" = 6; taper "d4460" = 0 deg
node "作業平面1"
sketch "スケッチ291"
  geometry: L1 (31.8, 20)-(31.8, 14.5) reference; L2 (31.8, 14.5)-(31.8, 24); L3 (31.8, 24)-(19.8, 24); L4 (30.8, 24)-(12.264, 24) reference; L5 (31.8, 14.5)-(19.8, 24); L6 (31.8, 24)-(31.8, 14.5); L7 (30.8, -20)-(30.8, 20) reference; 1 further point
  constraints: 8 end point, 1 parallel, 1 point on line, 1 vertical
  dimensions: "d4464" = 12 distance of L2.end L3.end
extrude "押し出し273" cut sketch "スケッチ291" distance "d4465" = 6; taper "d4466" = 0 deg
node "作業平面2"
sketch "スケッチ292"
  geometry: L1 (19, 0)-(19, 40) reference; L2 (19, 32)-(19, 40); L3 (19, 40)-(11, 40); L4 (19, 40)-(-34, 40) reference; L5 (19, 32)-(11, 40); L6 (11, 40)-(19, 40); L7 (18, 40)-(18, 36) reference; 1 further point
  constraints: 8 end point, 2 point on line, 1 collinear, 1 perpendicular
  dimensions: "d4468" = 8 distance of L1.end L3.end; "d4501" = 8 distance from line of L4 L2.start
extrude "押し出し274" cut sketch "スケッチ292" distance "d4469" = 4; taper "d4470" = 0 deg
sketch "スケッチ293"
  geometry: L1 (-79.412, -16.314)-(-79.412, 10.686) reference; L2 (-79.412, 10.686)-(-95.412, 10.686); L3 (-95.412, 10.686)-(-95.412, 6.686); L4 (-95.412, 6.686)-(-79.412, 6.686); L5 (-79.412, 6.686)-(-79.412, 10.686); L6 (19.588, 40.686)-(23.588, 40.686); L7 (23.588, 40.686)-(23.588, 56.686); L8 (23.588, 56.686)-(19.588, 56.686); L9 (19.588, 56.686)-(19.588, 40.686); L10 (111.588, 40.686)-(131.588, 40.686); L11 (131.588, 40.686)-(131.588, 46.686); L12 (131.588, 46.686)-(111.588, 46.686); L13 (111.588, 46.686)-(111.588, 40.686); L14 (119.588, -39.314)-(119.588, 40.686) reference; L15 (119.588, -39.314)-(131.588, -39.314); L16 (131.588, -39.314)-(131.588, -33.314); L17 (131.588, -33.314)-(119.588, -33.314); L18 (119.588, -33.314)-(119.588, -39.314); L19 (137.588, -55.314)-(131.588, -55.314); L20 (131.588, -55.314)-(131.588, -17.314); L21 (131.588, -17.314)-(137.588, -17.314); L22 (137.588, -17.314)-(137.588, -55.314); 1 further point
  constraints: 40 end point, 10 parallel, 5 horizontal, 5 perpendicular
  dimensions: "d4471" = 4 distance of L2.end L3.end; "d4472" = 16 distance of L1.end L2.end; "d4473" = 4 distance of L7.end L8.end; "d4474" = 16 distance of L8.end L6.start; "d4475" = 6 distance of L10.end L11.end; "d4476" = 20 distance of L11.end L12.end; "d4477" = 12 distance between parallel lines of L14 L11; "d4478" = 12 distance of L14.start L15.end; "d4479" = 6 distance of L15.end L16.end; "d4480" = 6 distance of L20.end L21.end; "d4481" = 16 distance between parallel lines of L15 L19; "d4482" = 16 distance between parallel lines of L21 L17
extrude "押し出し275" join sketch "スケッチ293" distance "d4483" = 4; taper "d4484" = 0 deg
sketch "スケッチ294"
  geometry: L1 (0, 20)-(-5, 20) reference; L2 (-4.5, 20)-(-0.5, 20); L3 (-0.5, 20)-(-0.5, 26); L4 (-0.5, 26)-(-4.5, 26); L5 (-4.5, 26)-(-4.5, 20); L6 (-5, 20)-(-5, 40) reference; L7 (0, 0)-(0, 20) reference; C1 r 2 at (-2.5, 26); 1 further point
  constraints: 8 end point, 2 parallel, 1 centre point, 1 horizontal, 1 midpoint, 1 perpendicular, 1 point on line
  dimensions: "d4485" = 6 distance from line of L1 C1.centre; "d4486" = 0.5 distance between parallel lines of L5 L6; "d4487" = 0.5 distance between parallel lines of L7 L3; "d4488" = 4 diameter of C1
extrude "押し出し276" cut sketch "スケッチ294" distance "d4489" = 8; taper "d4490" = 0 deg
sketch "スケッチ295"
  geometry: L1 (0.514, 0)-(0.514, 36) reference; L2 (0.514, 20)-(3.5, 20); L3 (3.5, 20)-(3.5, 26); L4 (3.5, 26)-(0.514, 26); L5 (0.514, 26)-(0.514, 20); L6 (4, 20)-(4, 16) reference; L7 (2, 36)-(2, 0) reference; L8 (0, 20)-(4, 20) reference; C1 r 1.5 at (2, 26); 1 further point
  constraints: 8 end point, 3 point on line, 2 parallel, 1 centre point, 1 horizontal, 1 perpendicular
  dimensions: "d4491" = 0.5 distance between parallel lines of L3 L6; "d4492" = 6 distance between parallel lines of L2 L4; "d4493" = 3 diameter of C1; "d4508" = 0 distance between parallel lines of L8 L2
extrude "押し出し277" cut sketch "スケッチ295" distance "d4494" = 6; taper "d4495" = 0 deg
node "作業平面3"
sketch "スケッチ297"
  geometry: L1 (1, 36)-(1, 0) reference; L2 (1, 20)-(3.452, 20); L3 (3.452, 20)-(8.8, 34); L4 (8.8, 34)-(1, 34); L5 (1, 40)-(1, 36) reference; L6 (1, 20)-(1, 34); L7 (0.5, 22.6)-(0.5, 24.8) reference; L8 (0, 20)-(4, 20) reference; L9 (26, 32)-(1, 32) reference; 1 further point
  constraints: 8 end point, 2 parallel, 2 point on line, 1 horizontal
  dimensions: "d4503" = 0 distance between parallel lines of L8 L2; "d4504" = 2 distance between parallel lines of L9 L4; "d4505" = 7.8 distance of L3.end L4.end
extrude "押し出し279" cut sketch "スケッチ297" distance "d4506" = 5; taper "d4507" = 0 deg
sketch "スケッチ298"
  geometry: L1 (-73.412, -1.314)-(-73.412, -19.314) reference; L2 (-73.412, -19.314)-(-20.412, -19.314) reference; C1 r 4 at (-63.412, -9.314); 1 further point
  constraints: 1 centre point
  dimensions: "d4509" = 8 diameter of C1; "d4510" = 10 distance from line of L1 C1.centre; "d4511" = 10 distance from line of C1.centre L2
extrude "押し出し280" join sketch "スケッチ298" distance "d4512" = 6; taper "d4513" = 0 deg
sketch "スケッチ299"
  geometry: L1 (41, 1)-(42.5, 1); L2 (42.5, 1)-(42.5, -2); L3 (42.5, -2)-(41, -2); L4 (41, -2)-(41, 1); L5 (43.5, 1)-(45, 1); L6 (45, 1)-(45, -2); L7 (45, -2)-(43.5, -2); L8 (43.5, -2)-(43.5, 1); L9 (53, -40)-(53, 0) reference; L10 (0, 0)-(52, 0) reference; L11 (15, -4)-(52, -4) reference; 1 further point
  constraints: 16 end point, 4 parallel, 2 horizontal, 2 perpendicular, 2 point on line
  dimensions: "d4514" = 1.5 distance of L1.start L1.end; "d4515" = 1 distance between parallel lines of L8 L2; "d4516" = 1.5 distance of L5.start L5.end; "d4517" = 8 distance between parallel lines of L9 L6; "d4518" = 3 distance of L5.end L6.end; "d4522" = 2 distance between parallel lines of L11 L7
extrude "押し出し281" cut sketch "スケッチ299" distance "d4520" = 20; taper "d4521" = 0 deg
sketch "スケッチ300"
  geometry: C1 r 6 at (0, 0); 1 further point
  constraints: 1 centre point
  dimensions: "d4523" = 12 diameter of C1
extrude "押し出し282" join sketch "スケッチ300" distance "d4524" = 20; taper "d4525" = -30 deg
sketch "スケッチ301"
  geometry: L1 (-73.412, 10.686)-(-73.412, 2.686) reference; L2 (-54.412, 10.686)-(-73.412, 10.686) reference; L3 (-19.412, 10.686)-(-19.412, 20.686) reference; L4 (-19.412, 20.686)-(-39.412, 20.686) reference; L5 (-73.412, -1.314)-(-73.412, -19.314) reference; L6 (-73.412, -19.314)-(-20.412, -19.314) reference; C1 r 0.6 at (-65.412, 5.686); C2 r 0.6 at (-53.412, 5.686); C3 r 0.6 at (-27.412, 12.686); C4 r 0.6 at (-39.412, 12.686); C5 r 0.6 at (-47.412, -13.314); 1 further point
  constraints: 5 centre point
  dimensions: "d4526" = 1.2 diameter of C1; "d4527" = 1.2 diameter of C2; "d4528" = 1.2 diameter of C4; "d4529" = 1.2 diameter of C3; "d4530" = 8 distance from line of C1.centre L1; "d4531" = 5 distance from line of L2 C1.centre; "d4532" = 0 vertical distance of C1.centre C2.centre; "d4533" = 12 distance of C1.centre C2.centre; "d4534" = 8 distance from line of C3.centre L3; "d4535" = 8 distance from line of C3.centre L4; "d4536" = 12 distance of C3.centre C4.centre; "d4537" = 0 vertical distance of C4.centre C3.centre; "d4538" = 1.2 diameter of C5; "d4539" = 26 distance from line of L5 C5.centre; "d4540" = 6 distance from line of C5.centre L6
extrude "押し出し283" join sketch "スケッチ301" distance "d4541" = 5; taper "d4542" = 0 deg
sketch "スケッチ302"
  geometry: C1 r 0.6 at (0, 0) reference; C2 r 5 at (0, 0); C3 r 0.6 at (-12, 0) reference; C4 r 5 at (-12, 0); C5 r 0.6 at (-26, -7) reference; C6 r 4 at (-26, -7); C7 r 0.6 at (-38, -7) reference; C8 r 4 at (-38, -7); C9 r 0.6 at (-20, -26) reference; C10 r 5 at (-20, -26); 1 further point
  constraints: 5 centre point, 5 coincident
  dimensions: "d4543" = 10 diameter of C10; "d4544" = 10 diameter of C2; "d4545" = 10 diameter of C4; "d4546" = 8 diameter of C6; "d4547" = 8 diameter of C8
extrude "押し出し284" join sketch "スケッチ302" distance "d4548" = 6; taper "d4549" = 0 deg
fillet "フィレット18" dims "d4550" = 3
fillet "フィレット19" dims "d4551" = 1
sketch "スケッチ303"
  geometry: L1 (-30.412, -18.314)-(-30.412, 19.686) reference; L2 (-73.412, -19.314)-(-20.412, -19.314) reference; C1 r 0.8 at (-28.412, -13.314); 1 further point
  constraints: 1 centre point
  dimensions: "d4552" = 1.6 diameter of C1; "d4553" = 2 distance from line of L1 C1.centre; "d4554" = 6 distance from line of C1.centre L2
extrude "押し出し285" join sketch "スケッチ303" distance "d4555" = 8; taper "d4556" = 0 deg
sketch "スケッチ304"
  geometry: C1 r 0.8 at (0, 0) reference; C2 r 6 at (0, 0); 1 further point
  constraints: 1 centre point, 1 coincident
  dimensions: "d4557" = 12 diameter of C2
extrude "押し出し286" join sketch "スケッチ304" distance "d4558" = 32; taper "d4559" = 0 deg
fillet "フィレット20" dims "d4560" = 3
fillet "フィレット21" dims "d4561" = 6
sketch "スケッチ306"
  geometry: L1 (18.588, 51.686)-(6.588, 51.686); L2 (6.588, 51.686)-(6.588, 55.686); L3 (6.588, 55.686)-(18.588, 55.686); L4 (18.588, 55.686)-(18.588, 51.686); L5 (133.588, 32.686)-(121.588, 32.686); L6 (121.588, 32.686)-(121.588, 36.686); L7 (121.588, 36.686)-(133.588, 36.686); L8 (133.588, 36.686)-(133.588, 32.686); L9 (133.588, 24.686)-(121.588, 24.686); L10 (121.588, 24.686)-(121.588, 28.686); L11 (121.588, 28.686)-(133.588, 28.686); L12 (133.588, 28.686)-(133.588, 24.686); L13 (133.588, 16.686)-(121.588, 16.686); L14 (121.588, 16.686)-(121.588, 20.686); L15 (121.588, 20.686)-(133.588, 20.686); L16 (133.588, 20.686)-(133.588, 16.686); L17 (130.588, -43.314)-(118.588, -43.314); L18 (118.588, -43.314)-(118.588, -47.314); L19 (118.588, -47.314)-(130.588, -47.314); L20 (130.588, -47.314)-(130.588, -43.314); L21 (19.588, 56.686)-(19.588, 40.686) reference; L22 (23.588, 56.686)-(19.588, 56.686) reference; L23 (137.588, -17.314)-(137.588, -55.314) reference; L24 (119.588, 40.686)-(131.588, 40.686) reference; L25 (131.588, -55.314)-(131.588, -39.314) reference; L26 (114.588, -39.314)-(131.588, -39.314) reference; 1 further point
  constraints: 40 end point, 10 parallel, 5 horizontal, 5 perpendicular, 4 point on line
  dimensions: "d4577" = 4 distance of L1.end L2.end; "d4578" = 12 distance of L2.end L3.end; "d4579" = 1 distance between parallel lines of L4 L21; "d4580" = 1 distance between parallel lines of L22 L3; "d4581" = 12 distance of L6.end L7.end; "d4582" = 4 distance of L7.end L5.start; "d4583" = 4 distance of L11.end L9.start; "d4584" = 4 distance of L15.end L13.start; "d4585" = 4 distance between parallel lines of L5 L11; "d4586" = 4 distance between parallel lines of L9 L15; "d4587" = 4 distance between parallel lines of L16 L23; "d4588" = 4 distance between parallel lines of L24 L7; "d4589" = 12 distance of L18.end L19.end; "d4590" = 4 distance of L17.end L18.end; "d4591" = 1 distance between parallel lines of L20 L25; "d4592" = 4 distance between parallel lines of L26 L17
extrude "押し出し288" join sketch "スケッチ306" distance "d4593" = 4; taper "d4594" = 0 deg
fillet "フィレット24" dims "d4595" = 2
fillet "フィレット25" dims "d4596" = 2
sketch "スケッチ307"
  geometry: L1 (16.588, 55.686)-(16.588, 51.686) reference; L2 (8.588, 51.686)-(8.588, 55.686) reference; L3 (16.588, 52.486)-(8.588, 52.486); L4 (8.588, 52.486)-(8.588, 54.886); L5 (8.588, 54.886)-(16.588, 54.886); L6 (16.588, 54.886)-(16.588, 52.486); L7 (16.588, 51.686)-(8.588, 51.686) reference; L8 (8.588, 55.686)-(16.588, 55.686) reference; L9 (131.588, 36.686)-(131.588, 32.686) reference; L10 (123.588, 32.686)-(123.588, 36.686) reference; L11 (131.588, 33.486)-(123.588, 33.486); L12 (123.588, 33.486)-(123.588, 35.886); L13 (123.588, 35.886)-(131.588, 35.886); L14 (131.588, 35.886)-(131.588, 33.486); L15 (131.588, 25.486)-(123.588, 25.486); L16 (123.588, 25.486)-(123.588, 27.886); L17 (123.588, 27.886)-(131.588, 27.886); L18 (131.588, 27.886)-(131.588, 25.486); L19 (123.588, 16.686)-(123.588, 20.686) reference; L20 (131.588, 17.486)-(123.588, 17.486); L21 (123.588, 17.486)-(123.588, 19.886); L22 (123.588, 19.886)-(131.588, 19.886); L23 (131.588, 19.886)-(131.588, 17.486); L24 (123.588, 36.686)-(131.588, 36.686) reference; L25 (131.588, 32.686)-(123.588, 32.686) reference; L26 (123.588, 28.686)-(131.588, 28.686) reference; L27 (131.588, 24.686)-(123.588, 24.686) reference; L28 (123.588, 20.686)-(131.588, 20.686) reference; L29 (131.588, 16.686)-(123.588, 16.686) reference; L30 (120.588, -47.314)-(120.588, -43.314) reference; L31 (128.543, -46.514)-(120.588, -46.514); L32 (120.588, -46.514)-(120.588, -44.114); L33 (120.588, -44.114)-(128.543, -44.114); L34 (128.543, -44.114)-(128.543, -46.514); L35 (128.588, -43.314)-(120.588, -43.314) reference; L36 (120.588, -47.314)-(128.588, -47.314) reference; 1 further point
  constraints: 40 end point, 10 parallel, 9 point on line, 5 horizontal, 5 perpendicular
  dimensions: "d4597" = 0.8 distance between parallel lines of L3 L7; "d4598" = 0.8 distance between parallel lines of L8 L5; "d4599" = 0.8 distance between parallel lines of L24 L13; "d4600" = 0.8 distance between parallel lines of L25 L11; "d4601" = 0.8 distance between parallel lines of L26 L17; "d4602" = 0.8 distance between parallel lines of L27 L15; "d4603" = 0.8 distance between parallel lines of L28 L22; "d4604" = 0.8 distance between parallel lines of L29 L20; "d4605" = 0.8 distance between parallel lines of L35 L33; "d4606" = 0.8 distance between parallel lines of L36 L31
extrude "押し出し289" cut sketch "スケッチ307" distance "d4607" = 1; taper "d4608" = 0 deg
sketch "スケッチ308"
  geometry: L1 (128.543, -44.114)-(128.543, -46.514) reference; L2 (120.588, -47.314)-(128.588, -47.314) reference; L3 (123.588, 36.686)-(131.588, 36.686) reference; L4 (123.588, 28.686)-(131.588, 28.686) reference; L5 (123.588, 20.686)-(131.588, 20.686) reference; L6 (123.588, 33.486)-(123.588, 35.886) reference; L7 (8.588, 52.486)-(8.588, 54.886) reference; L8 (16.588, 51.686)-(8.588, 51.686) reference; C1 r 0.5 at (122.543, -45.314); C2 r 0.5 at (125.588, 18.686); C3 r 0.5 at (125.588, 26.686); C4 r 0.5 at (125.588, 34.686); C5 r 0.5 at (10.588, 53.686); 1 further point
  constraints: 5 centre point
  dimensions: "d4609" = 1 diameter of C1; "d4610" = 6 distance from line of L1 C1.centre; "d4611" = 2 distance from line of C1.centre L2; "d4612" = 1 diameter of C2; "d4613" = 1 diameter of C3; "d4614" = 1 diameter of C4; "d4615" = 2 distance from line of C4.centre L3; "d4616" = 2 distance from line of C3.centre L4; "d4617" = 2 distance from line of C2.centre L5; "d4618" = 2 distance from line of C4.centre L6; "d4619" = 0 horizontal distance of C4.centre C3.centre; "d4620" = 0 horizontal distance of C2.centre C3.centre; "d4621" = 1 diameter of C5; "d4622" = 2 distance from line of C5.centre L7; "d4623" = 2 distance from line of C5.centre L8
extrude "押し出し290" join sketch "スケッチ308" distance "d4624" = 10; taper "d4625" = 0 deg
fillet "フィレット26" dims "d4626" = 0.5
